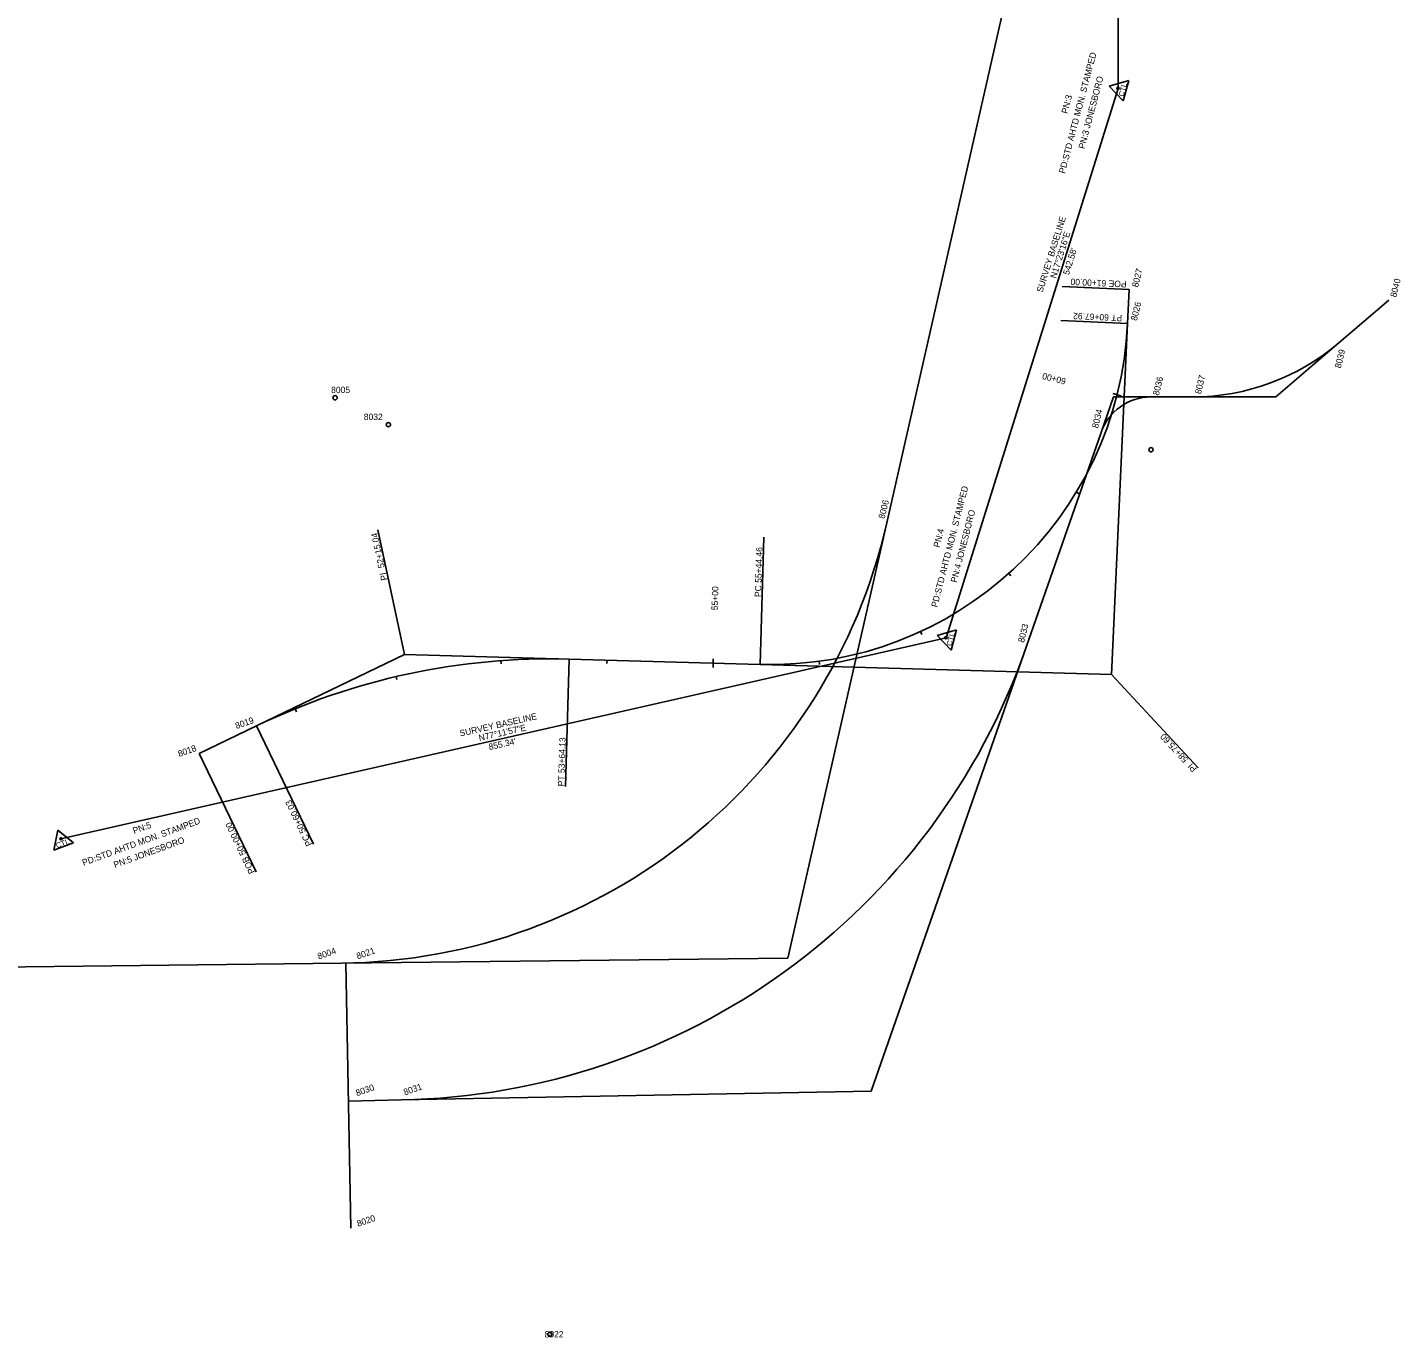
# Model space of a CAD drawing. Extents: x 1710417 to 1716352, y 548603 to 551217.
# Drawn here: x 1711437 to 1712731, y 548860 to 550094 of the extents above; entities that cross this region are included whole.
import ezdxf

# ---------------------------------------------------------------- set-up
doc = ezdxf.new("R2010")
doc.units = 0
for name, color, linetype in [('G-ANNO-TEXT', 7, 'Continuous'), ('R_Horz Alg', 7, 'Continuous'), ('R_Horz Alg Annot', 7, 'Continuous'), ('S_BASELINE', 7, 'Continuous'), ('S_BASELINE_ANNOT', 7, 'Continuous'), ('S_PRIMARY_CTL_ANNOT', 7, 'Continuous')]:
    doc.layers.add(name, color=color, linetype=linetype)

msp = doc.modelspace()

# ---------------------------------------------------------------- linework, layer by layer
at = {"layer": 'G-ANNO-TEXT'}
for p, q in [((1712456.4, 550039.1), (1712474.9, 550044.4)), ((1712469.8, 550025.2), (1712474.9, 550044.4)), ((1712456.4, 550039.1), (1712469.8, 550025.2)), ((1712294.3, 549521.3), (1712312.7, 549526.6)), ((1712307.7, 549507.4), (1712312.7, 549526.6)), ((1712294.3, 549521.3), (1712307.7, 549507.4)), ((1711465.6, 549337.7), (1711461.9, 549318.8)), ((1711465.6, 549337.7), (1711480.5, 549325.7)), ((1711461.9, 549318.8), (1711480.5, 549325.7))]:
    msp.add_line(p, q, dxfattribs=at)
for centre, radius in [((1712464.8, 550036.9), 1.04), ((1712464.8, 550036.9), 0.609), ((1712464.8, 550036.9), 0.344), ((1712302.7, 549519.1), 1.04), ((1712302.7, 549519.1), 0.609), ((1712302.7, 549519.1), 0.344), ((1711468.6, 549329.6), 1.04), ((1711468.6, 549329.6), 0.609), ((1711468.6, 549329.6), 0.344)]:
    msp.add_circle(centre, radius, dxfattribs=at)
at = {"layer": 'R_Horz Alg'}
for p, q in [((1712246.8, 549627.3), (1712450.8, 550525.8)), ((1712473.8, 549815.3), (1712475.3, 549847.4)), ((1712673, 549797.1), (1712719.9, 549837.2)), ((1712495.9, 549746.1), (1712535, 549746.1)), ((1712378.3, 549510.2), (1712448.9, 549712.7)), ((1711947.4, 549499), (1712127.6, 549493.9)), ((1711598.7, 549409.9), (1711652.8, 549436)), ((1711391.8, 549208.5), (1711733, 549212.4)), ((1711741.8, 548962.5), (1711737.1, 549212.4)), ((1711739.5, 549082.4), (1711789.2, 549083.4))]:
    msp.add_line(p, q, dxfattribs=at)
for centre, radius, start, end in [((1712137.1, 549830.8), 337, 268.3826, 357.3716), ((1712535, 549958.3), 212.2, 270, 310.5648), ((1712495.9, 549696.3), 49.8, 90, 160.7734), ((1711727, 549745.3), 533, 270.6428, 347.2066), ((1711777.2, 549719.9), 636.6, 271.0787, 340.7734), ((1711929.4, 548862.6), 636.6, 88.3826, 115.7513)]:
    msp.add_arc(centre, radius, start, end, dxfattribs=at)
at = {"layer": 'R_Horz Alg Annot'}
for p, q in [((1712458.6, 549484.5), (1712473.8, 549815.3)), ((1712613.4, 549746.1), (1712673, 549797.1)), ((1712448.9, 549712.7), (1712460.5, 549746.1)), ((1712460.5, 549746.1), (1712495.9, 549746.1)), ((1712535, 549746.1), (1712613.4, 549746.1)), ((1712153.6, 549217.1), (1712246.8, 549627.3)), ((1712232.3, 549091.7), (1712378.3, 549510.2)), ((1711652.8, 549436), (1711792.4, 549503.3)), ((1711792.4, 549503.3), (1711947.4, 549499)), ((1712127.6, 549493.9), (1712458.6, 549484.5)), ((1711733, 549212.4), (1712153.6, 549217.1)), ((1711789.2, 549083.4), (1712232.3, 549091.7))]:
    msp.add_line(p, q, dxfattribs=at)
for points in [[(1712475.3, 549847.4), (1712412.3, 549850.2)], [(1712473.8, 549815.3), (1712410.8, 549818.2)], [(1712460, 549749.2), (1712467.8, 549747.2)], [(1712428.1, 549654.7), (1712425.5, 549656.3)], [(1711792.4, 549503.3), (1711767.3, 549620.7)], [(1712127.6, 549493.9), (1712131, 549613.8)], [(1712363.9, 549577.4), (1712361.9, 549579.6)], [(1712279.9, 549522.2), (1712278.6, 549524.9)], [(1711883.5, 549494.5), (1711883.3, 549497.5)], [(1711947.4, 549499), (1711944, 549379)], [(1711983.1, 549494.9), (1711983.2, 549497.9)], [(1712083.3, 549499.1), (1712083.1, 549491.1)], [(1712183.4, 549493.9), (1712183, 549496.9)], [(1712458.6, 549484.5), (1712540.3, 549396.6)], [(1711785.2, 549479.6), (1711784.5, 549482.5)], [(1711690.5, 549449.4), (1711689.3, 549452.2)], [(1711652.8, 549436), (1711706.6, 549324.5)], [(1711598.7, 549409.9), (1711652.5, 549298.4)]]:
    msp.add_lwpolyline(points, dxfattribs=at)
for centre in [(1711727, 549745.3), (1711777.2, 549719.9), (1712495.9, 549696.3), (1711929.4, 548862.6)]:
    msp.add_circle(centre, 2, dxfattribs=at)
at = {"layer": 'S_BASELINE'}
for p, q in [((1712464.8, 550036.9), (1712465.4, 550547.8)), ((1712302.7, 549519.1), (1712464.8, 550036.9)), ((1711468.6, 549329.6), (1712302.7, 549519.1))]:
    msp.add_line(p, q, dxfattribs=at)

# ---------------------------------------------------------------- texts
at = {"layer": 'G-ANNO-TEXT'}
for rotation, p in [(75.243, (1712470, 550028.7)), (75.4956, (1712307.9, 549510.9)), (20.3519, (1711464.9, 549320.6))]:
    msp.add_text('CTL', height=5, rotation=rotation, dxfattribs=at).set_placement(p)
at = {"layer": 'R_Horz Alg Annot'}
for s, rotation, p in [('8027', 75.9935, (1712483.6, 549848.9)), ('POE 61+00.00', 177.3716, (1712473, 549855.2)), ('8040', 75.9935, (1712727, 549839.5)), ('8026', 75.9935, (1712482.5, 549817.5)), ('PT 60+67.92', 177.3716, (1712468.8, 549823.3)), ('8039', 75.9935, (1712674.7, 549772.7)), ('60+00', 165.8246, (1712416.2, 549763.4)), ('8036', 75.9935, (1712503.2, 549747)), ('8037', 75.9935, (1712542.9, 549748.4)), ('8034', 75.9935, (1712445.9, 549716.2)), ('8006', 75.9935, (1712244.7, 549630.8)), ('PI  52+15.04', 102.0669, (1711776.3, 549573.7)), ('PC 55+44.46', 88.3826, (1712128.4, 549557.4)), ('55+00', 88.3826, (1712087.6, 549545)), ('8033', 75.9935, (1712376.2, 549514.1)), ('8019', 19.3572, (1711634.1, 549433)), ('PT 53+64.13', 88.3826, (1711943, 549379)), ('PI  58+75.60', 132.8771, (1712539.5, 549395.9)), ('8018', 19.3572, (1711580, 549406.7)), ('PC 50+60.03', 115.7513, (1711705.6, 549324.4)), ('POB 50+00.00', 115.7513, (1711651.6, 549298.3)), ('8004', 19.3572, (1711711.6, 549215.7)), ('8021', 19.3572, (1711748.3, 549215.9)), ('8030', 19.3572, (1711747.6, 549086.9)), ('8031', 19.3572, (1711792.7, 549087.7)), ('8020', 19.3572, (1711748.7, 548963.8))]:
    msp.add_text(s, height=6, rotation=rotation, dxfattribs=at).set_placement(p)
for s, p in [('8005', (1711723.2, 549749.7)), ('8032', (1711754, 549724.3)), ('8022', (1711924.4, 548859.6))]:
    msp.add_text(s, height=6, dxfattribs=at).set_placement(p)
at = {"layer": 'S_BASELINE_ANNOT'}
for s, rotation, p in [('SURVEY BASELINE', 72.6123, (1712393.6, 549844.1)), ('N17%%d23\'16"E', 72.6123, (1712406.4, 549857.3)), ("542.58'", 72.6123, (1712418.5, 549860.6)), ('SURVEY BASELINE', 12.8007, (1711845, 549425.9)), ('N77%%d11\'57"E', 12.8007, (1711863, 549421.6)), ("855.34'", 12.8007, (1711872.4, 549413.1))]:
    msp.add_text(s, height=6, rotation=rotation, dxfattribs=at).set_placement(p)
at = {"layer": 'S_PRIMARY_CTL_ANNOT'}
for s, rotation, p in [('PD:STD AHTD MON. STAMPED', 75.2755, (1712414.7, 549956.2)), ('PN:3 JONESBORO', 75.2755, (1712433.2, 549979.4)), ('PN:3', 75.2755, (1712417.1, 550012.6)), ('PD:STD AHTD MON. STAMPED', 75.5633, (1712294.4, 549547.3)), ('PN:4 JONESBORO', 75.5633, (1712312.8, 549570.6)), ('PN:4', 75.5633, (1712296.5, 549603.7)), ('PD:STD AHTD MON. STAMPED', 19.9941, (1711489.9, 549304)), ('PN:5', 19.9941, (1711537.6, 549334.1)), ('PN:5 JONESBORO', 19.9941, (1711519.5, 549302))]:
    msp.add_text(s, height=6, rotation=rotation, dxfattribs=at).set_placement(p)

doc.saveas('drawing.dxf')
